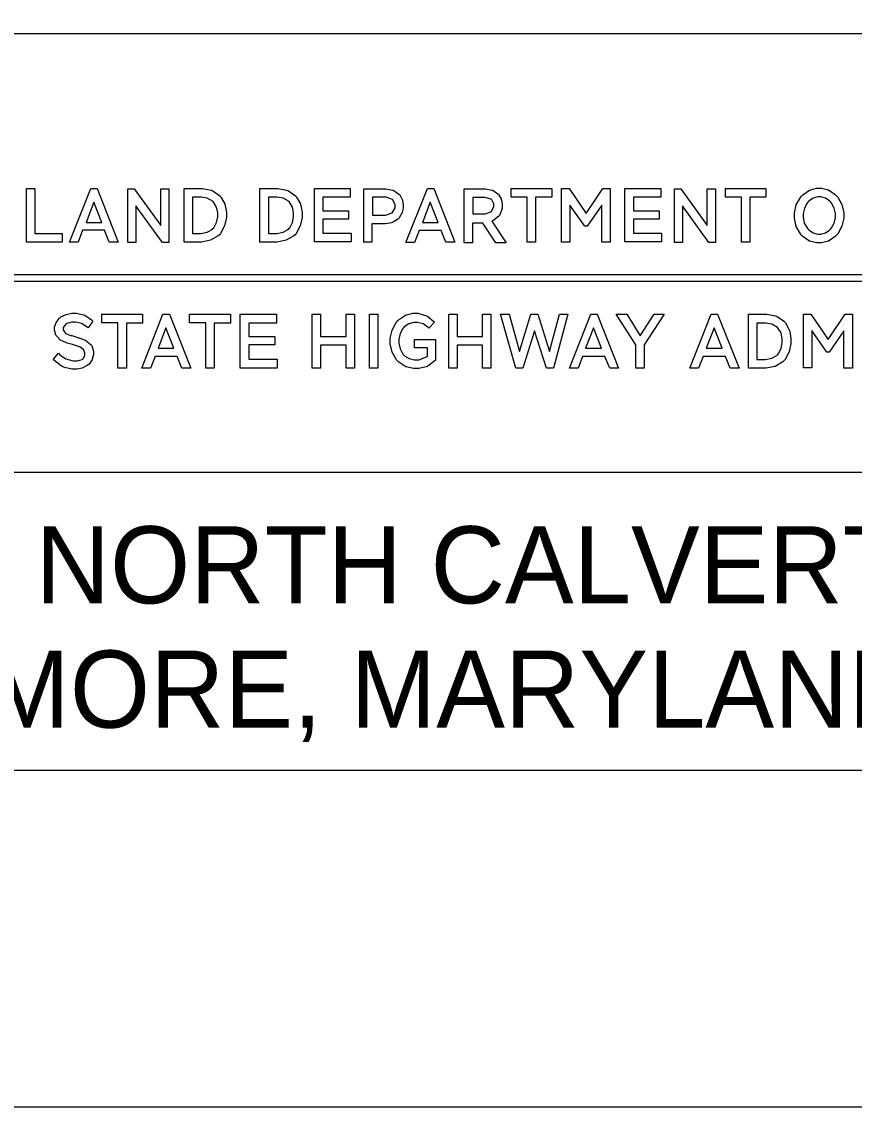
# Model space of a CAD drawing. Extents: x -1 to 9.2, y 0 to 14.8.
# Drawn here: x 3.799 to 4.663, y 0 to 1.127 of the extents above; entities that cross this region are included whole.
import ezdxf

# ---------------------------------------------------------------- set-up
doc = ezdxf.new("R2010")
doc.units = 0
for name, color, linetype in [('G-BORD-LINE', 7, 'Continuous'), ('G-MSHA-LOGO', 7, 'Continuous'), ('G-USER-LINE', 7, 'Continuous'), ('G-USER-PAGE', 7, 'Continuous')]:
    doc.layers.add(name, color=color, linetype=linetype)

msp = doc.modelspace()

# ---------------------------------------------------------------- linework, layer by layer
at = {"layer": 'G-BORD-LINE'}
msp.add_lwpolyline([(0.35, 0.8607), (0.35, 0.35), (8.15, 0.35), (8.15, 10.65), (0.35, 10.65), (0.35, 0.8607)], dxfattribs=at)
at = {"layer": 'G-MSHA-LOGO'}
for points in [[(3.8038, 0.9534), (3.8125, 0.9534), (3.8125, 0.9068), (3.841, 0.9068), (3.841, 0.8979), (3.8038, 0.8979)], [(3.8706, 0.9534), (3.8772, 0.9534), (3.8991, 0.8979), (3.8899, 0.8979), (3.885, 0.9102), (3.8622, 0.9102), (3.8574, 0.8979), (3.8487, 0.8979)], [(3.9452, 0.8976), (3.9175, 0.9356), (3.9175, 0.8976), (3.9092, 0.8976), (3.9092, 0.9531), (3.9158, 0.9531), (3.9434, 0.9151), (3.9434, 0.9531), (3.9518, 0.9531), (3.9518, 0.8976)], [(3.9676, 0.9534), (3.9831, 0.9534), (3.9865, 0.9534), (3.9955, 0.9518), (3.9964, 0.9514), (3.9973, 0.951), (4.0047, 0.946), (4.0053, 0.9454), (4.0058, 0.9447), (4.0097, 0.9375), (4.0099, 0.9367), (4.0101, 0.9359), (4.0114, 0.9287), (4.0114, 0.9263), (4.0114, 0.9235), (4.0096, 0.9149), (4.0054, 0.907), (4.0042, 0.9056), (4.0029, 0.9043), (3.9951, 0.8998), (3.9855, 0.8979), (3.9823, 0.8979), (3.9676, 0.8979)], [(4.0462, 0.9534), (4.0617, 0.9534), (4.065, 0.9534), (4.074, 0.9518), (4.075, 0.9514), (4.0759, 0.951), (4.0833, 0.946), (4.0839, 0.9454), (4.0844, 0.9447), (4.0883, 0.9375), (4.0885, 0.9367), (4.0887, 0.9359), (4.09, 0.9287), (4.09, 0.9263), (4.09, 0.9235), (4.0882, 0.9149), (4.084, 0.907), (4.0828, 0.9056), (4.0815, 0.9043), (4.0736, 0.8998), (4.0641, 0.8979), (4.0609, 0.8979), (4.0462, 0.8979)], [(4.1029, 0.9534), (4.14, 0.9534), (4.14, 0.9445), (4.1116, 0.9445), (4.1116, 0.9304), (4.1383, 0.9304), (4.1383, 0.9217), (4.1116, 0.9217), (4.1116, 0.9071), (4.1409, 0.9071), (4.1409, 0.8982), (4.1029, 0.8982)], [(4.1541, 0.8976), (4.1541, 0.9531), (4.1743, 0.9531), (4.1769, 0.9531), (4.1839, 0.9519), (4.1847, 0.9517), (4.1854, 0.9514), (4.1906, 0.9478), (4.191, 0.9474), (4.1914, 0.9469), (4.194, 0.9421), (4.1942, 0.9416), (4.1943, 0.9411), (4.195, 0.9365), (4.195, 0.935), (4.195, 0.9333), (4.1941, 0.9289), (4.1939, 0.9284), (4.1937, 0.9279), (4.1908, 0.9231), (4.1904, 0.9226), (4.1901, 0.9222), (4.1845, 0.9186), (4.1838, 0.9183), (4.1831, 0.918), (4.1763, 0.9169), (4.174, 0.9169), (4.1625, 0.9169), (4.1625, 0.8979), (4.1541, 0.8979)], [(4.2201, 0.9534), (4.2267, 0.9534), (4.2486, 0.8979), (4.2394, 0.8979), (4.2345, 0.9099), (4.2117, 0.9099), (4.2068, 0.8976), (4.1979, 0.8976)], [(4.2584, 0.8976), (4.2584, 0.9531), (4.2779, 0.9531), (4.2804, 0.9531), (4.287, 0.9519), (4.2877, 0.9517), (4.2884, 0.9515), (4.2934, 0.9481), (4.2938, 0.9477), (4.2941, 0.9472), (4.2967, 0.9427), (4.2969, 0.9422), (4.2971, 0.9417), (4.2978, 0.9371), (4.2978, 0.9356), (4.2978, 0.9331), (4.2954, 0.9262), (4.2949, 0.9255), (4.2944, 0.9248), (4.2877, 0.9197), (4.2869, 0.9195), (4.3018, 0.8973), (4.2912, 0.8973), (4.2776, 0.9177), (4.267, 0.9177), (4.267, 0.8973), (4.2584, 0.8973)], [(4.307, 0.9534), (4.3493, 0.9534), (4.3493, 0.9445), (4.3323, 0.9445), (4.3323, 0.8979), (4.3237, 0.8979), (4.3237, 0.9445), (4.307, 0.9445)], [(4.3594, 0.9534), (4.3672, 0.9534), (4.385, 0.9275), (4.4023, 0.9534), (4.4098, 0.9534), (4.4098, 0.8979), (4.4011, 0.8979), (4.4011, 0.9364), (4.3859, 0.9143), (4.3836, 0.9143), (4.368, 0.9364), (4.368, 0.8979), (4.3594, 0.8979)], [(4.4253, 0.9534), (4.4625, 0.9534), (4.4625, 0.9445), (4.434, 0.9445), (4.434, 0.9304), (4.4607, 0.9304), (4.4607, 0.9217), (4.434, 0.9217), (4.434, 0.9071), (4.4633, 0.9071), (4.4633, 0.8982), (4.4253, 0.8982)], [(4.5125, 0.8976), (4.4849, 0.9356), (4.4849, 0.8976), (4.4766, 0.8976), (4.4766, 0.9531), (4.4832, 0.9531), (4.5108, 0.9151), (4.5108, 0.9531), (4.5192, 0.9531), (4.5192, 0.8976)], [(4.5292, 0.9534), (4.5716, 0.9534), (4.5716, 0.9445), (4.5549, 0.9445), (4.5549, 0.8979), (4.5462, 0.8979), (4.5462, 0.9445), (4.5295, 0.9445), (4.5295, 0.9534)], [(4.6087, 0.9457), (4.6099, 0.947), (4.6169, 0.9519), (4.6243, 0.954), (4.6268, 0.954), (4.6293, 0.954), (4.6367, 0.952), (4.6437, 0.9473), (4.645, 0.9459), (4.6462, 0.9446), (4.6505, 0.9368), (4.6524, 0.9283), (4.6524, 0.9255), (4.6524, 0.9227), (4.6505, 0.9143), (4.6462, 0.9064), (4.645, 0.9051), (4.6437, 0.9037), (4.6367, 0.899), (4.6293, 0.897), (4.6268, 0.897), (4.6243, 0.897), (4.6169, 0.899), (4.6099, 0.9037), (4.6087, 0.9051), (4.6075, 0.9064), (4.6031, 0.9142), (4.6012, 0.9227), (4.6012, 0.9255), (4.6012, 0.9283), (4.6031, 0.9366), (4.6075, 0.9443)], [(3.8657, 0.9183), (3.8821, 0.9183), (3.8738, 0.9393)], [(3.9763, 0.9442), (3.9763, 0.9068), (3.9829, 0.9068), (3.985, 0.9068), (3.9915, 0.9081), (3.9967, 0.9111), (3.9975, 0.912), (3.9983, 0.9128), (4.0012, 0.9182), (4.0024, 0.9243), (4.0024, 0.9263), (4.0024, 0.9283), (4.0012, 0.9343), (3.9976, 0.94), (3.9916, 0.9434), (3.9853, 0.9445), (3.9831, 0.9445), (3.9763, 0.9445)], [(4.0551, 0.9442), (4.0551, 0.9068), (4.0617, 0.9068), (4.0639, 0.9068), (4.0704, 0.9081), (4.0756, 0.9111), (4.0764, 0.912), (4.0772, 0.9128), (4.0801, 0.9182), (4.0813, 0.9243), (4.0813, 0.9263), (4.0813, 0.9283), (4.0801, 0.9343), (4.0765, 0.94), (4.0705, 0.9434), (4.0641, 0.9445), (4.062, 0.9445), (4.0551, 0.9445)], [(4.1631, 0.9445), (4.1631, 0.9258), (4.1746, 0.9258), (4.1768, 0.9258), (4.1837, 0.9282), (4.1867, 0.9335), (4.1867, 0.9353), (4.1867, 0.937), (4.1838, 0.9422), (4.1773, 0.9445), (4.1752, 0.9445)], [(4.2149, 0.9183), (4.2313, 0.9183), (4.223, 0.9393)], [(4.2673, 0.9442), (4.2673, 0.9272), (4.2785, 0.9272), (4.2804, 0.9272), (4.2858, 0.9292), (4.2863, 0.9295), (4.2867, 0.9299), (4.2892, 0.9346), (4.2892, 0.9361), (4.2892, 0.9377), (4.287, 0.9418), (4.2866, 0.9422), (4.2861, 0.9425), (4.2802, 0.9442), (4.2782, 0.9442)], [(4.6153, 0.9117), (4.6161, 0.9108), (4.6207, 0.9075), (4.6255, 0.9062), (4.6271, 0.9062), (4.6287, 0.9062), (4.6335, 0.9075), (4.6381, 0.9108), (4.6389, 0.9117), (4.6397, 0.9126), (4.6425, 0.9177), (4.6438, 0.9236), (4.6438, 0.9255), (4.6438, 0.9275), (4.6425, 0.9333), (4.6397, 0.9385), (4.6389, 0.9393), (4.6381, 0.9403), (4.6335, 0.9435), (4.6287, 0.9448), (4.6271, 0.9448), (4.6255, 0.9448), (4.6207, 0.9435), (4.6161, 0.9403), (4.6153, 0.9393), (4.6145, 0.9385), (4.6117, 0.9333), (4.6104, 0.9275), (4.6104, 0.9255), (4.6104, 0.9236), (4.6115, 0.9177), (4.6144, 0.9126)], [(3.5786, 0.8643), (5.4382, 0.8643), (5.4382, 0.8571), (3.5786, 0.8571)], [(3.8629, 0.7866), (3.8626, 0.7869), (3.8589, 0.7892), (3.8584, 0.7895), (3.8579, 0.7896), (3.8528, 0.7913), (3.8522, 0.7914), (3.8516, 0.7916), (3.846, 0.7932), (3.8455, 0.7934), (3.8449, 0.7936), (3.8398, 0.7959), (3.8393, 0.7962), (3.8388, 0.7965), (3.8351, 0.8005), (3.8348, 0.801), (3.8345, 0.8015), (3.8331, 0.8066), (3.8331, 0.8083), (3.8331, 0.8098), (3.8346, 0.8144), (3.8378, 0.8188), (3.8387, 0.8195), (3.8396, 0.8203), (3.845, 0.8229), (3.8511, 0.824), (3.8531, 0.824), (3.8559, 0.824), (3.8643, 0.822), (3.8715, 0.8172), (3.8727, 0.8159), (3.868, 0.8088), (3.8669, 0.8098), (3.861, 0.8133), (3.8548, 0.8147), (3.8528, 0.8147), (3.8509, 0.8147), (3.8457, 0.8134), (3.8452, 0.8131), (3.8447, 0.8128), (3.8421, 0.8092), (3.8421, 0.808), (3.8421, 0.8069), (3.844, 0.8039), (3.8444, 0.8035), (3.8447, 0.8032), (3.8496, 0.8011), (3.8503, 0.801), (3.8509, 0.8009), (3.8571, 0.799), (3.8578, 0.7987), (3.8585, 0.7985), (3.8649, 0.7961), (3.8654, 0.7959), (3.866, 0.7956), (3.8709, 0.7914), (3.8713, 0.7909), (3.8717, 0.7903), (3.8736, 0.7846), (3.8736, 0.7827), (3.8736, 0.7811), (3.8721, 0.776), (3.8689, 0.7714), (3.868, 0.7706), (3.867, 0.7699), (3.8617, 0.7671), (3.8561, 0.7659), (3.8542, 0.7659), (3.851, 0.7659), (3.8423, 0.7682), (3.8413, 0.7687), (3.8402, 0.7692), (3.8323, 0.7753), (3.8317, 0.776), (3.8371, 0.7827), (3.8382, 0.7814), (3.8449, 0.7766), (3.8525, 0.7746), (3.855, 0.7746), (3.8568, 0.7746), (3.8616, 0.776), (3.8621, 0.7763), (3.8625, 0.7765), (3.8646, 0.7801), (3.8646, 0.7813), (3.8646, 0.7826), (3.8632, 0.7864)], [(3.8817, 0.8232), (3.9244, 0.8232), (3.9244, 0.8139), (3.9076, 0.8139), (3.9076, 0.767), (3.8989, 0.767), (3.8989, 0.8142), (3.882, 0.8142), (3.882, 0.8232)], [(3.9455, 0.8232), (3.9523, 0.8232), (3.9745, 0.767), (3.9652, 0.767), (3.9604, 0.7793), (3.9374, 0.7793), (3.9326, 0.767), (3.9236, 0.767)], [(3.973, 0.8232), (4.0158, 0.8232), (4.0158, 0.8139), (3.9989, 0.8139), (3.9989, 0.767), (3.9902, 0.767), (3.9902, 0.8142), (3.9733, 0.8142), (3.9733, 0.8232)], [(4.0259, 0.8232), (4.0635, 0.8232), (4.0635, 0.8139), (4.0346, 0.8139), (4.0346, 0.7999), (4.0616, 0.7999), (4.0616, 0.7912), (4.0346, 0.7912), (4.0346, 0.7763), (4.0641, 0.7763), (4.0641, 0.767), (4.0259, 0.767)], [(4.1358, 0.7909), (4.1093, 0.7909), (4.1093, 0.767), (4.1006, 0.767), (4.1006, 0.8232), (4.1093, 0.8232), (4.1093, 0.7999), (4.1358, 0.7999), (4.1358, 0.8232), (4.1445, 0.8232), (4.1445, 0.767), (4.1358, 0.767)], [(4.1599, 0.8232), (4.1686, 0.8232), (4.1686, 0.767), (4.1599, 0.767)], [(4.2066, 0.797), (4.2285, 0.797), (4.2285, 0.7754), (4.2279, 0.7747), (4.2206, 0.7693), (4.2198, 0.7689), (4.2189, 0.7685), (4.2111, 0.7667), (4.2085, 0.7667), (4.2058, 0.7667), (4.1978, 0.7686), (4.1904, 0.7732), (4.1891, 0.7746), (4.1879, 0.7759), (4.1834, 0.7837), (4.1816, 0.7925), (4.1816, 0.7954), (4.1816, 0.7982), (4.1834, 0.8066), (4.1877, 0.8145), (4.1889, 0.8159), (4.1901, 0.8173), (4.1973, 0.8221), (4.2049, 0.824), (4.2074, 0.824), (4.2103, 0.824), (4.2183, 0.8219), (4.2192, 0.8215), (4.2201, 0.8211), (4.2269, 0.8154), (4.2274, 0.8147), (4.2215, 0.8086), (4.2207, 0.8096), (4.2158, 0.813), (4.2099, 0.8145), (4.208, 0.8145), (4.2062, 0.8145), (4.2008, 0.8132), (4.1961, 0.81), (4.1953, 0.8091), (4.1946, 0.8083), (4.1918, 0.8031), (4.1905, 0.7971), (4.1905, 0.7951), (4.1905, 0.7931), (4.1918, 0.787), (4.1948, 0.7817), (4.1956, 0.7807), (4.1964, 0.7799), (4.2013, 0.777), (4.2067, 0.7757), (4.2085, 0.7757), (4.2114, 0.7757), (4.2193, 0.779), (4.2201, 0.7796), (4.2201, 0.7883), (4.2066, 0.7883)], [(4.2774, 0.7909), (4.251, 0.7909), (4.251, 0.767), (4.2423, 0.767), (4.2423, 0.8232), (4.251, 0.8232), (4.251, 0.7999), (4.2774, 0.7999), (4.2774, 0.8232), (4.2861, 0.8232), (4.2861, 0.767), (4.2774, 0.767)], [(4.351, 0.767), (4.3437, 0.767), (4.3313, 0.806), (4.3193, 0.767), (4.3119, 0.767), (4.2962, 0.8232), (4.3052, 0.8232), (4.3159, 0.7844), (4.3277, 0.8232), (4.3347, 0.8232), (4.3468, 0.7844), (4.3572, 0.8232), (4.3659, 0.8232)], [(4.3898, 0.8232), (4.3965, 0.8232), (4.4187, 0.767), (4.4095, 0.767), (4.4044, 0.7793), (4.3813, 0.7793), (4.3766, 0.767), (4.3676, 0.767)], [(4.4451, 0.7914), (4.4451, 0.767), (4.4364, 0.767), (4.4364, 0.7914), (4.4162, 0.8232), (4.4272, 0.8232), (4.4412, 0.8007), (4.4555, 0.8232), (4.4659, 0.8232)], [(4.5147, 0.8232), (4.5215, 0.8232), (4.5437, 0.767), (4.5344, 0.767), (4.5296, 0.7793), (4.5066, 0.7793), (4.5018, 0.767), (4.4928, 0.767)], [(4.5535, 0.8232), (4.5692, 0.8232), (4.5725, 0.8232), (4.5815, 0.8213), (4.5825, 0.8209), (4.5834, 0.8206), (4.5909, 0.8154), (4.5914, 0.8147), (4.592, 0.8141), (4.5959, 0.8069), (4.5962, 0.806), (4.5965, 0.8052), (4.5976, 0.798), (4.5976, 0.7956), (4.5976, 0.7928), (4.5958, 0.7841), (4.5915, 0.7762), (4.5903, 0.7748), (4.5891, 0.7735), (4.5812, 0.7689), (4.5716, 0.767), (4.5684, 0.767), (4.5535, 0.767)], [(4.6106, 0.8232), (4.6184, 0.8232), (4.6364, 0.797), (4.6538, 0.8232), (4.6614, 0.8232), (4.6614, 0.767), (4.6527, 0.767), (4.6527, 0.806), (4.6373, 0.7838), (4.635, 0.7838), (4.6193, 0.8063), (4.6193, 0.7673), (4.6106, 0.7673)], [(4.5622, 0.8139), (4.5622, 0.776), (4.569, 0.776), (4.5711, 0.776), (4.5777, 0.7773), (4.583, 0.7804), (4.5839, 0.7813), (4.5847, 0.7822), (4.5875, 0.7876), (4.5886, 0.7937), (4.5886, 0.7956), (4.5886, 0.7976), (4.5874, 0.8036), (4.5838, 0.8093), (4.5777, 0.8128), (4.5714, 0.8139), (4.5692, 0.8139)], [(3.9405, 0.7878), (3.957, 0.7878), (3.9486, 0.8091)], [(4.3844, 0.7878), (4.401, 0.7878), (4.3926, 0.8091)], [(4.5097, 0.7878), (4.5263, 0.7878), (4.5178, 0.8091)]]:
    msp.add_lwpolyline(points, close=True, dxfattribs=at)
at = {"layer": 'G-USER-LINE'}
msp.add_lwpolyline([(5.5468, 0.6588), (2.9468, 0.6588), (2.9468, 1.1144), (5.5468, 1.1144)], close=True, dxfattribs=at)
at = {"layer": 'G-USER-PAGE'}
msp.add_lwpolyline([(0, 11), (8.5, 11), (8.5, 0), (0, 0)], close=True, dxfattribs=at)

# ---------------------------------------------------------------- texts
at = {"layer": 'G-BORD-LINE'}
for s, p in [('707 NORTH CALVERT ST.', (3.6052, 0.523)), ('BALTIMORE, MARYLAND 21202', (3.4626, 0.394))]:
    msp.add_text(s, height=0.079998, dxfattribs=at).set_placement(p)

doc.saveas('drawing.dxf')
